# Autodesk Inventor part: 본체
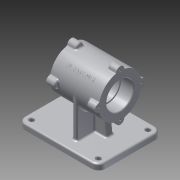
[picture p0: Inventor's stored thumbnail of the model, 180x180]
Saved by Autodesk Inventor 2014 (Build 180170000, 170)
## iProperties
Created: 2015-12
Part Number: 본체
Material: 알루미늄 6061
Document SubType Name: Modeling
Designer: aapexcom
Density: 2.71 g/cm^3
Appearance: 알루미늄 - 평지
Mass: 1167.38 g
Surface Area: 816.713 cm^2
Volume: 430.768 cm^3
Author: aapexcom
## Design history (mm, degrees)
sketch "스케치1"
  geometry: L1 (-70, 55)-(70, 55); L2 (70, 55)-(70, -55); L3 (70, -55)-(-70, -55); L4 (-70, -55)-(-70, 55); 1 further point
  constraints: 8 end point, 2 parallel, 1 horizontal, 1 perpendicular
  dimensions: "d0" = 140 distance of L2.end L3.end; "d1" = 110 distance of L1.end L2.end; "d2" = 55 distance from line of L1 point (0, 0) (= 0.5 x d1); "d3" = 70 distance from line of point (0, 0) L2 (= 0.5 x d0)
extrude "돌출1" new body sketch "스케치1" distance "d4" = 10; taper "d5" = 0 deg
fillet "모깎기1" dims "d6" = 12
sketch "스케치2"
  geometry: C1 r 4 at (-58, 43); C2 r 4 at (-58, -43); C3 r 4 at (58, -43); C4 r 4 at (58, 43); A1 r 12 centre (-58, 43) between (-58, 55) and (-70, 43) reference; A2 r 12 centre (-58, -43) between (-70, -43) and (-58, -55) reference; A3 r 12 centre (58, -43) between (58, -55) and (70, -43) reference; A4 r 12 centre (58, 43) between (70, 43) and (58, 55) reference; 1 further point
  constraints: 4 centre point, 4 coincident
  dimensions: "d7" = 8 diameter of C1; "d8" = 8 diameter of C2; "d9" = 8 diameter of C3; "d10" = 8 diameter of C4
extrude "돌출2" cut sketch "스케치2" stored distance "d11" = 10; taper "d12" = 0 deg
node "작업 평면1"
sketch "스케치4"
  geometry: L1 (98, 0)-(-12, 0) reference; L2 (-12, 0)-(-12, 10) reference; L3 (-12, 10)-(98, 10) reference; L4 (98, 10)-(98, 0) reference; L5 (6, 10)-(80, 10); L6 (80, 10)-(80, 80); L7 (80, 80)-(6, 80); L8 (6, 80)-(6, 10); 1 further point
  constraints: 8 end point, 2 parallel, 1 horizontal, 1 perpendicular, 1 point on line
  dimensions: "d14" = 70 distance of L5.end L6.end; "d15" = 74 distance of L6.end L7.end; "d16" = 37 distance from line of point (43, 0) L6 (= 0.5 x d15)
extrude "돌출3" join sketch "스케치4" stored distance "d17" = 8; taper "d18" = 0 deg
sketch "스케치5"
  geometry: L1 (70, 10)-(70, 0) reference; L2 (70, 0)-(-70, 0) reference; L3 (-70, 0)-(-70, 10) reference; L4 (-70, 10)-(-14, 10) reference; L5 (-14, 10)-(-14, 80) reference; L6 (-14, 80)-(-6, 80) reference; L7 (-6, 80)-(-6, 10) reference; L8 (-6, 10)-(70, 10) reference; L9 (-35, 10)-(-26.329, 80.616); L10 (15, 10)-(6.329, 80.616); L11 (-10, 80)-(-10, 0); L12 (-26.329, 80.616)-(6.329, 80.616); L13 (-35, 10)-(15, 10); 1 further point
  constraints: 10 end point, 3 point on line, 2 perpendicular, 1 collinear, 1 midpoint
  dimensions: "d19" = 97 deg angle of L4 L9; "d20" = 97 deg angle of L10 L8; "d21" = 25 horizontal distance of L11.end L10.start; "d22" = 25 horizontal distance of L9.start L11.end
extrude "돌출4" join sketch "스케치5" stored distance "d23" = 12; taper "d24" = 0 deg
node "작업 평면2"
sketch "스케치6"
  geometry: L1 (0, 0)-(86, 0) reference; C1 r 37 at (43, 80); 1 further point
  constraints: 1 centre point, 1 vertical alignment
  dimensions: "d26" = 74 diameter of C1; "d27" = 80 distance from line of L1 C1.centre
extrude "돌출5" join sketch "스케치6" distance "d28" = 85; taper "d29" = 0 deg
sketch "스케치7"
  geometry: C1 r 37 at (0, 0) reference; C2 r 23.5 at (0, 0); 1 further point
  constraints: 1 centre point, 1 coincident
  dimensions: "d30" = 47 diameter of C2
extrude "돌출6" cut sketch "스케치7" distance "d31" = 22; taper "d32" = 0 deg
chamfer "모따기1" distance "d33" = 1; stored, may be unused: second distance "d34" = 2, angle "d35" = 45 deg
fillet "모깎기2" dims "d36" = 0.3
sketch "스케치8"
  geometry: C1 r 37 at (0, 0) reference; C2 r 23.5 at (0, 0); 1 further point
  constraints: 1 centre point, 1 coincident
  dimensions: "d37" = 47 diameter of C2
extrude "돌출7" cut sketch "스케치8" distance "d38" = 22; taper "d39" = 0 deg
chamfer "모따기2" distance "d40" = 1; stored, may be unused: second distance "d41" = 2, angle "d42" = 45 deg
fillet "모깎기3" dims "d43" = 0.3
sketch "스케치9"
  geometry: C1 r 23.2 at (0, 0) reference; C2 r 21 at (0, 0); 1 further point
  constraints: 1 centre point, 1 coincident
  dimensions: "d44" = 42 diameter of C2
extrude "돌출8" cut sketch "스케치9" distance "d45" = 41; taper "d46" = 0 deg
sketch "스케치10"
  geometry: L1 (80, 55)-(80, -55) reference; L2 (80, -55)-(70, -55) reference; L3 (70, -55)-(70, 55) reference; L4 (70, 55)-(80, 55) reference; C1 r 24.5 at (0, 0) reference; C2 r 37 at (0, 0) reference; C3 r 37 at (0, 0) reference; C4 r 24.5 at (0, 0) reference; C5 r 7 at (-37, 0.001); C6 r 7 at (-0.017, -37); C7 r 7 at (-0.001, 37); C8 r 7 at (37, 0.001); 1 further point
  constraints: 4 centre point
  dimensions: "d47" = 14 diameter of C5; "d48" = 14 diameter of C6; "d50" = 14 diameter of C7; "d51" = 14 diameter of C8
extrude "돌출9" join sketch "스케치10" distance "d52" = 15; taper "d53" = 0 deg
sketch "스케치11"
  geometry: C1 r 7 at (37, 0.001); C2 r 7 at (0.017, -37); C3 r 7 at (-37, 0.001); C4 r 7 at (0.001, 37); A1 r 37 centre (0, 0) between (36.338, -6.968) and (36.338, 6.969) reference; A2 r 7 centre (37, 0.001) between (36.338, -6.968) and (36.338, 6.969) reference; A3 r 37 centre (0, 0) between (6.97, 36.338) and (-6.967, 36.338) reference; A4 r 7 centre (0.001, 37) between (6.97, 36.338) and (-6.967, 36.338) reference; A5 r 37 centre (0, 0) between (-6.952, -36.341) and (6.985, -36.335) reference; A6 r 7 centre (0.017, -37) between (-6.952, -36.341) and (6.985, -36.335) reference; A7 r 7 centre (-37, 0.001) between (-36.338, 6.97) and (-36.338, -6.967) reference; 1 further point
  constraints: 4 centre point, 4 coincident
  dimensions: "d54" = 14 diameter of C1; "d55" = 14 diameter of C2; "d56" = 14 diameter of C3; "d57" = 14 diameter of C4
extrude "돌출10" join sketch "스케치11" distance "d58" = 15; taper "d59" = 0 deg
sketch "스케치12"
  geometry: A1 r 7 centre (-80.001, 80) between (-73.033, 79.338) and (-86.97, 79.338) reference; A2 r 7 centre (-117, 43.001) between (-116.338, 49.969) and (-116.338, 36.032) reference; A3 r 7 centre (-80.017, 6) between (-86.985, 6.665) and (-73.048, 6.659) reference; A4 r 7 centre (-43, 43.001) between (-43.662, 36.033) and (-43.662, 49.97) reference; 5 further points
  constraints: 4 coincident
hole "구멍1" sketch "스케치12" at (-80.001, 80), (-117, 43.001), (-43, 43.001), (-80.017, 6) diameter "d60" = 3.242; stored, may be unused: countersink angle "d64" = 90 deg, drill point angle "d66" = 118 deg; dims "d61" = 9, "d62" = 4, "d63" = 2, "d65" = 11
sketch "스케치13"
  geometry: A1 r 7 centre (43, 43.001) between (43.662, 49.97) and (43.662, 36.033) reference; A2 r 7 centre (80.017, 6) between (73.048, 6.659) and (86.985, 6.665) reference; A3 r 7 centre (117, 43.001) between (116.338, 36.032) and (116.338, 49.969) reference; A4 r 7 centre (80.001, 80) between (86.97, 79.338) and (73.033, 79.338) reference; 5 further points
  constraints: 4 coincident
hole "구멍2" sketch "스케치13" at (80.001, 80), (117, 43.001), (80.017, 6), (43, 43.001) diameter "d67" = 3.242; stored, may be unused: countersink angle "d71" = 90 deg, drill point angle "d73" = 118 deg; dims "d68" = 9, "d69" = 4, "d70" = 2, "d72" = 11
fillet "모깎기4" dims "d74" = 3
fillet "모깎기5" dims "d75" = 3
fillet "모깎기6" dims "d76" = 3
fillet "모깎기7" dims "d77" = 3
sketch "스케치14"
  geometry: L1 (-30.5, 56.8)-(-30.5, 59) reference; L2 (-30.5, 59)-(10.5, 59) reference; L3 (10.5, 59)-(10.5, 56.8) reference; L4 (10.8, 56.5)-(31.5, 56.5) reference; L5 (31.5, 56.5)-(32.5, 55.5) reference; L6 (32.5, 55.5)-(32.5, 44.621) reference; L7 (32.5, 44.621)-(21.5, 44.621) reference; L8 (21.5, 41.379)-(32.5, 41.379) reference; L9 (32.5, 41.379)-(32.5, 36) reference; L10 (32.5, 36)-(20.5, 36) reference; L11 (17.5, 39)-(17.5, 40) reference; L12 (14.5, 43)-(14.339, 43) reference; L13 (11.361, 39.634)-(14.677, 12.634) reference; L14 (17.654, 10)-(67, 10) reference; L15 (70, 7)-(70, 0) reference; L16 (70, 0)-(-70, 0) reference; L17 (-70, 0)-(-70, 7) reference; L18 (-67, 10)-(-37.654, 10) reference; L19 (-34.677, 12.634)-(-31.361, 39.634) reference; L20 (-34.339, 43)-(-34.5, 43) reference; L21 (-37.5, 40)-(-37.5, 39) reference; L22 (-40.5, 36)-(-52.5, 36) reference; L23 (-52.5, 36)-(-52.5, 41.379) reference; L24 (-52.5, 41.379)-(-41.5, 41.379) reference; L25 (-41.5, 44.621)-(-52.5, 44.621) reference; L26 (-52.5, 44.621)-(-52.5, 55.5) reference; L27 (-52.5, 55.5)-(-51.5, 56.5) reference; L28 (-51.5, 56.5)-(-30.8, 56.5) reference; L29 (-30.8, 103.5)-(-51.5, 103.5) reference; L30 (-51.5, 103.5)-(-52.5, 104.5) reference; L31 (-52.5, 104.5)-(-52.5, 115.379) reference; L32 (-52.5, 115.379)-(-41.5, 115.379) reference; L33 (-41.5, 118.621)-(-52.5, 118.621) reference; L34 (-52.5, 118.621)-(-52.5, 124) reference; L35 (-52.5, 124)-(-40.5, 124) reference; L36 (-37.5, 121)-(-37.5, 120) reference; L37 (-34.5, 117)-(14.5, 117) reference; L38 (17.5, 120)-(17.5, 121) reference; L39 (20.5, 124)-(32.5, 124) reference; L40 (32.5, 124)-(32.5, 118.621) reference; L41 (32.5, 118.621)-(21.5, 118.621) reference; L42 (21.5, 115.379)-(32.5, 115.379) reference; L43 (32.5, 115.379)-(32.5, 104.5) reference; L44 (32.5, 104.5)-(31.5, 103.5) reference; L45 (31.5, 103.5)-(10.8, 103.5) reference; L46 (10.5, 103.2)-(10.5, 101) reference; L47 (10.5, 101)-(-30.5, 101) reference; L48 (-30.5, 101)-(-30.5, 103.2) reference; L49 (-10, 0)-(-10, 117); L50 (-52.5, 104.5)-(-52.5, 55.5) reference; L51 (-52.5, 80)-(-10, 80); L52 (-52.5, 80)-(-71.352, 80); A1 r 0.3 centre (-30.8, 56.8) between (-30.8, 56.5) and (-30.5, 56.8) reference; A2 r 0.3 centre (10.8, 56.8) between (10.5, 56.8) and (10.8, 56.5) reference; A3 r 3 centre (14.5, 40) between (17.5, 40) and (14.5, 43) reference; A4 r 3 centre (17.654, 13) between (14.677, 12.634) and (17.654, 10) reference; A5 r 3 centre (67, 7) between (70, 7) and (67, 10) reference; A6 r 3 centre (-67, 7) between (-67, 10) and (-70, 7) reference; A7 r 3 centre (-37.654, 13) between (-37.654, 10) and (-34.677, 12.634) reference; A8 r 3 centre (-34.5, 40) between (-34.5, 43) and (-37.5, 40) reference; A9 r 0.3 centre (-30.8, 103.2) between (-30.5, 103.2) and (-30.8, 103.5) reference; A10 r 3 centre (-34.5, 120) between (-37.5, 120) and (-34.5, 117) reference; A11 r 3 centre (14.5, 120) between (14.5, 117) and (17.5, 120) reference; A12 r 0.3 centre (10.8, 103.2) between (10.8, 103.5) and (10.5, 103.2) reference; 1 further point
  constraints: 6 end point, 4 vertical alignment, 2 midpoint, 2 point on line, 1 collinear, 1 perpendicular, 6 other
  node "절단 모서리 투영4"
node "작업 평면4"
  node "작업 평면3"
sketch "스케치15"
  geometry: L1 (-85, 18.922)-(-85, -18.907) reference; 3 further points
  constraints: 1 horizontal alignment, 1 midpoint, 1 other
  dimensions: "d80" = 42.5 distance from line of L1 point (-42.5, 0.007)
feature "엠보싱1" sketch "스케치15" dims "d0" = 140, "d1" = 110, "d2" = 55 (= 0.5 x d1), "d3" = 70 (= 0.5 x d0), "d81" = 0.5, "d82" = 0
chamfer "모따기3" distance "d83" = 1; stored, may be unused: second distance "d84" = 2, angle "d85" = 45 deg
node "솔리드1"
node "투영된 루프1"
node "투영된 루프2"
node "투영된 루프3"
node "절단 모서리 투영1"
node "절단 모서리 투영2"
node "절단 모서리 투영3"
other parameters: "d25" = 42.5, "d78" = -45 deg
